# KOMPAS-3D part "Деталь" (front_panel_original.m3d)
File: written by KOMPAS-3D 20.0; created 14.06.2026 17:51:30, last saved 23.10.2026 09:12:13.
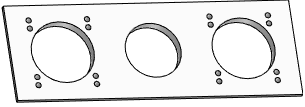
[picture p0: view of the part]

Document properties: Полное имя файла: D:\RicWork\Project-EPS32\box_compas\корпус\front_panel_original.m3d

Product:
- Part/product: Деталь
    Материал: Фанера, береза,ФСФ ВВ/С ГОСТ 3916.1-2018 (density 760 kg/m3)
    Масса: 0.0539472

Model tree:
1. Эскиз:1
2. Элемент выдавливания:1
     Расстояние 1 = 8
3. Фаска:1  (with: Элемент выдавливания:1)
     Угол = 45; Длина 1 = 5; Длина 2 = 5
4. Эскиз:2  (with: Элемент выдавливания:1)
5. Элемент выдавливания:2
     Расстояние 2 = 8
6. Эскиз:5  (with: Элемент выдавливания:1, Фаска:1)
7. Элемент выдавливания:5
     Расстояние 2 = 8
8. Эскиз:6  (with: Элемент выдавливания:1, Элемент выдавливания:2)
9. Элемент выдавливания:6
     Расстояние 2 = 8
10. Массив по сетке:1  (with: Элемент выдавливания:6, Эскиз:6)  (4 pattern instances)
     Шаг 1 = 42; Угол раствора = -90; Шаг 2 = 48
11. Смещенная плоскость:1  (with: Элемент выдавливания:1)
     Расстояние = -102.5
12. Зеркальный массив:1
13. Экземпляр ( 1 )
14. Экземпляр ( 2 )  (with: Массив по сетке:1, Экземпляр ( 1 ), Элемент выдавливания:6)
15. Эскиз:7  (with: Элемент выдавливания:1, Элемент выдавливания:2)
16. Элемент выдавливания:7
     Расстояние 2 = 8
17. Массив по сетке:2  (with: Элемент выдавливания:7, Эскиз:7)  (2 pattern instances)
     Шаг 1 = 42; Угол раствора = 90
18. Зеркальный массив:2  (with: Экземпляр ( 1 ), Экземпляр ( 2 ), Массив по сетке:2, Элемент выдавливания:7)  (labels: Фанера, береза,ФСФ ВВ/С ГОСТ 3916.1-2018)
